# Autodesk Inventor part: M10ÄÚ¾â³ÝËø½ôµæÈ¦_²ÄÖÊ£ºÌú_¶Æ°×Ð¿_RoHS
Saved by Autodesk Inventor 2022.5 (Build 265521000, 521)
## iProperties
Created: 2025-02
Part Number: M10ÄÚ¾â³ÝËø½ôµæÈ¦_²ÄÖÊ£ºÌú_¶Æ°×Ð¿_RoHS
Material: Generic
Document SubType Name: Modeling
Designer: AdminForWorker
Density: 1 g/cm^3
Appearance: Default
Title: M10ÄÚ¾â³ÝËø½ôµæÈ¦_²ÄÖÊ£ºÌú_¶Æ°×Ð¿_RoHS
Author: AdminForWorker
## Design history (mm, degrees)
feature "Body1"
body "Solid1"
